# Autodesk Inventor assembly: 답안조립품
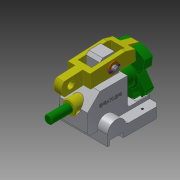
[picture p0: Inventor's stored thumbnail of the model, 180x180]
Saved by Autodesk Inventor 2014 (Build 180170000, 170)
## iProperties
Created: 2016-11
Part Number: 답안조립품
Document SubType Name: Assembly
Designer: USER
Author: USER
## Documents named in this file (8)
- C:\Users\USER\Desktop\461108V1025\답안조립품.iam
- C:\Users\USER\Desktop\461108V1025\본체.ipt
- C:\Users\USER\Desktop\461108V1025\부시.ipt
- C:\Users\USER\Desktop\461108V1025\분할대.ipt
- C:\Users\USER\Desktop\461108V1025\분할축.ipt
- C:\Users\USER\Desktop\461108V1025\와셔.ipt
- C:\Users\USER\Desktop\461108V1025\원통형핀.ipt
- C:\Users\USER\Desktop\461108V1025\클레비스핀.ipt
